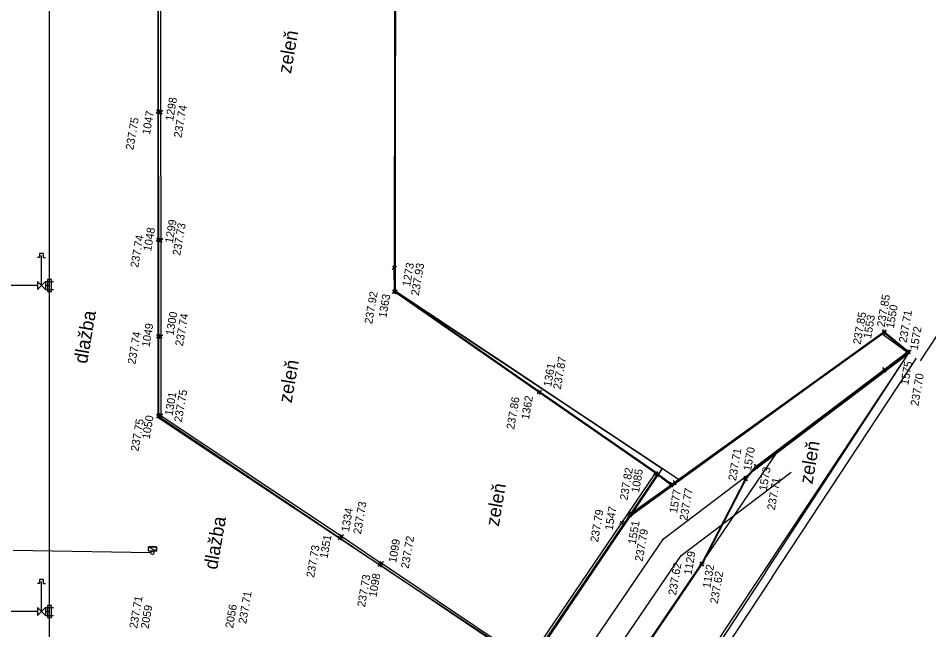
# Model space of a CAD drawing. Extents: x -264205 to -263659, y -1242401 to -1241986.
# Drawn here: x -263790.1 to -263733.2, y -1242222.2 to -1242184 of the extents above; entities that cross this region are included whole.
import ezdxf

# ---------------------------------------------------------------- set-up
doc = ezdxf.new("R2010")
doc.units = 0
for name, color, linetype in [('BOD_CISLO_2-4', 7, 'Continuous'), ('BOD_SYMBOL_2-4', 7, 'Continuous'), ('BOD_VYSKA_2-4', 7, 'Continuous'), ('POPIS_2-4', 7, 'Continuous'), ('PROJEKT_OBRUBNIKY_KOMUNIKACIE', 7, 'Continuous'), ('PROJEKT_TDZ_VODOROVNE', 7, 'Continuous'), ('SITUACIA_DSP_2D', 7, 'Continuous'), ('SO_20-4_OBRUBNIKY_HORNA_HRANA', 7, 'Continuous')]:
    doc.layers.add(name, color=color, linetype=linetype)

msp = doc.modelspace()

# ---------------------------------------------------------------- linework, layer by layer
at = {"layer": 'BOD_SYMBOL_2-4'}
for p, q in [((-263781.219, -1242189.759), (-263781.475, -1242189.939)), ((-263781.257, -1242189.977), (-263781.437, -1242189.721)), ((-263781.075, -1242189.76), (-263781.331, -1242189.94)), ((-263781.113, -1242189.978), (-263781.293, -1242189.722)), ((-263781.217, -1242197.765), (-263781.473, -1242197.945)), ((-263781.255, -1242197.983), (-263781.435, -1242197.727)), ((-263781.07, -1242197.772), (-263781.326, -1242197.952)), ((-263781.108, -1242197.99), (-263781.288, -1242197.734)), ((-263766.482, -1242199.494), (-263766.738, -1242199.674)), ((-263766.52, -1242199.712), (-263766.7, -1242199.456)), ((-263766.48, -1242200.997), (-263766.736, -1242201.177)), ((-263766.518, -1242201.215), (-263766.698, -1242200.959)), ((-263766.433, -1242200.971), (-263766.689, -1242201.151)), ((-263766.471, -1242201.189), (-263766.651, -1242200.933)), ((-263781.25, -1242204.002), (-263781.43, -1242203.746)), ((-263781.106, -1242203.995), (-263781.286, -1242203.739)), ((-263735.895, -1242203.532), (-263736.151, -1242203.712)), ((-263735.894, -1242203.473), (-263736.15, -1242203.653)), ((-263735.933, -1242203.75), (-263736.113, -1242203.494)), ((-263735.932, -1242203.691), (-263736.112, -1242203.435)), ((-263781.212, -1242203.784), (-263781.468, -1242203.964)), ((-263781.068, -1242203.777), (-263781.324, -1242203.957)), ((-263734.424, -1242204.724), (-263734.68, -1242204.904)), ((-263734.462, -1242204.942), (-263734.642, -1242204.686)), ((-263734.342, -1242204.73), (-263734.598, -1242204.91)), ((-263734.38, -1242204.948), (-263734.56, -1242204.692)), ((-263735.882, -1242205.839), (-263736.138, -1242206.019)), ((-263735.854, -1242205.87), (-263736.11, -1242206.05)), ((-263735.92, -1242206.057), (-263736.1, -1242205.801)), ((-263735.892, -1242206.088), (-263736.072, -1242205.832)), ((-263757.438, -1242207.266), (-263757.694, -1242207.446)), ((-263757.41, -1242207.227), (-263757.666, -1242207.407)), ((-263757.476, -1242207.484), (-263757.656, -1242207.228)), ((-263757.448, -1242207.445), (-263757.628, -1242207.189)), ((-263781.212, -1242208.754), (-263781.468, -1242208.934)), ((-263781.25, -1242208.972), (-263781.43, -1242208.716)), ((-263781.065, -1242208.713), (-263781.321, -1242208.893)), ((-263781.103, -1242208.931), (-263781.283, -1242208.675)), ((-263750.206, -1242212.532), (-263750.386, -1242212.276)), ((-263743.888, -1242211.879), (-263744.144, -1242212.059)), ((-263743.861, -1242211.918), (-263744.117, -1242212.098)), ((-263743.926, -1242212.097), (-263744.106, -1242211.841)), ((-263743.899, -1242212.136), (-263744.079, -1242211.88)), ((-263750.168, -1242212.314), (-263750.424, -1242212.494)), ((-263750.049, -1242212.397), (-263750.305, -1242212.577)), ((-263750.022, -1242212.357), (-263750.278, -1242212.537)), ((-263750.087, -1242212.615), (-263750.267, -1242212.359)), ((-263750.06, -1242212.575), (-263750.24, -1242212.319)), ((-263744.547, -1242212.631), (-263744.803, -1242212.811)), ((-263744.585, -1242212.849), (-263744.765, -1242212.593)), ((-263744.507, -1242212.655), (-263744.763, -1242212.835)), ((-263744.545, -1242212.873), (-263744.725, -1242212.617)), ((-263749.18, -1242213.024), (-263749.436, -1242213.204)), ((-263749.168, -1242213.053), (-263749.424, -1242213.233)), ((-263749.218, -1242213.242), (-263749.398, -1242212.986)), ((-263749.142, -1242213.001), (-263749.398, -1242213.181)), ((-263749.206, -1242213.271), (-263749.386, -1242213.015)), ((-263749.18, -1242213.219), (-263749.36, -1242212.963)), ((-263748.961, -1242212.903), (-263749.217, -1242213.083)), ((-263748.999, -1242213.121), (-263749.179, -1242212.865)), ((-263751.761, -1242214.922), (-263752.017, -1242215.102)), ((-263751.799, -1242215.14), (-263751.979, -1242214.884)), ((-263751.701, -1242214.833), (-263751.957, -1242215.013)), ((-263751.739, -1242215.051), (-263751.919, -1242214.795)), ((-263752.267, -1242215.425), (-263752.523, -1242215.605)), ((-263752.305, -1242215.643), (-263752.485, -1242215.387)), ((-263769.787, -1242216.25), (-263770.043, -1242216.43)), ((-263769.825, -1242216.468), (-263770.005, -1242216.212)), ((-263769.87, -1242216.372), (-263770.126, -1242216.552)), ((-263769.908, -1242216.59), (-263770.088, -1242216.334)), ((-263767.295, -1242217.924), (-263767.551, -1242218.104)), ((-263767.333, -1242218.142), (-263767.513, -1242217.886)), ((-263747.289, -1242217.967), (-263747.545, -1242218.147)), ((-263747.327, -1242218.185), (-263747.507, -1242217.929)), ((-263747.289, -1242218.21), (-263747.469, -1242217.954)), ((-263767.373, -1242218.042), (-263767.629, -1242218.222)), ((-263767.411, -1242218.26), (-263767.591, -1242218.004)), ((-263747.251, -1242217.992), (-263747.507, -1242218.172))]:
    msp.add_line(p, q, dxfattribs=at)
at = {"layer": 'PROJEKT_OBRUBNIKY_KOMUNIKACIE'}
for p, q in [((-263766.58, -1242201.01), (-263766.58, -1242144.85)), ((-263758.42, -1242206.43), (-263766.58, -1242201.01)), ((-263736.134, -1242203.7), (-263751.891, -1242215.1)), ((-263736.134, -1242203.7), (-263734.475, -1242204.91)), ((-263742.736, -1242211.145), (-263734.49, -1242204.937)), ((-263757.19, -1242207.25), (-263758.42, -1242206.43)), ((-263748.89, -1242212.77), (-263757.19, -1242207.25)), ((-263794.898, -1242288.032), (-263742.736, -1242211.145)), ((-263798.899, -1242284.125), (-263751.864, -1242215.081)), ((-263751.891, -1242215.1), (-263751.891, -1242215.1)), ((-263743.421, -1242218.608), (-263752.521, -1242232.37))]:
    msp.add_line(p, q, dxfattribs=at)
for points in [[(-263766.58, -1242083.485), (-263766.58, -1242201.01), (-263749.879, -1242212.113), (-263758.153, -1242224.365), (-263781.364, -1242208.936), (-263781.371, -1242084.903), (-263766.58, -1242083.485)], [(-263743.421, -1242218.608), (-263734.49, -1242204.937), (-263734.475, -1242204.91)]]:
    msp.add_lwpolyline(points, dxfattribs=at)
at = {"layer": 'PROJEKT_TDZ_VODOROVNE'}
for p, q in [((-263733.748, -1242205.389), (-263732.096, -1242202.886)), ((-263743.006, -1242218.884), (-263733.993, -1242205.228)), ((-263743.006, -1242218.884), (-263752.106, -1242232.646))]:
    msp.add_line(p, q, dxfattribs=at)
for points in [[(-263831.211, -1242326.873), (-263816.19, -1242319.41), (-263814.291, -1242315.804), (-263813.06, -1242301.353), (-263812.968, -1242299.181), (-263802.618, -1242291.831), (-263801.478, -1242290.893), (-263800.257, -1242289.755), (-263799.049, -1242288.464), (-263798.027, -1242287.218), (-263749.798, -1242216.488), (-263742.736, -1242211.145)], [(-263830.6, -1242328.105), (-263815.26, -1242320.378), (-263813.062, -1242316.188), (-263811.682, -1242301.389), (-263811.608, -1242300.055), (-263801.705, -1242293.023), (-263800.489, -1242292.021), (-263799.197, -1242290.817), (-263797.92, -1242289.454), (-263796.825, -1242288.118), (-263748.697, -1242217.536), (-263741.831, -1242212.341)]]:
    msp.add_lwpolyline(points, dxfattribs=at)
at = {"layer": 'SITUACIA_DSP_2D'}
for p, q in [((-263788.143, -1242250.14), (-263788.143, -1242082.64)), ((-263766.58, -1242083.485), (-263766.58, -1242201.01)), ((-263781.364, -1242208.936), (-263781.371, -1242084.903)), ((-263766.58, -1242201.01), (-263766.58, -1242144.85)), ((-263788.768, -1242198.932), (-263788.893, -1242198.932)), ((-263788.768, -1242198.682), (-263788.768, -1242198.932)), ((-263788.518, -1242198.682), (-263788.768, -1242198.682)), ((-263788.643, -1242200.682), (-263788.643, -1242198.807)), ((-263788.518, -1242198.932), (-263788.518, -1242198.682)), ((-263788.518, -1242198.932), (-263788.393, -1242198.932)), ((-263788.268, -1242200.307), (-263788.268, -1242201.057)), ((-263788.018, -1242200.307), (-263788.268, -1242200.307)), ((-263788.018, -1242201.057), (-263788.018, -1242200.307)), ((-263788.893, -1242200.682), (-263800.593, -1242200.682)), ((-263788.893, -1242200.432), (-263788.893, -1242200.932)), ((-263788.393, -1242200.932), (-263788.893, -1242200.432)), ((-263788.893, -1242200.932), (-263788.393, -1242200.432)), ((-263788.393, -1242200.432), (-263788.393, -1242200.932)), ((-263788.393, -1242200.432), (-263787.893, -1242200.432)), ((-263788.143, -1242200.682), (-263788.393, -1242200.682)), ((-263788.393, -1242200.682), (-263788.143, -1242200.682)), ((-263788.393, -1242200.932), (-263787.893, -1242200.932)), ((-263788.268, -1242201.057), (-263788.018, -1242201.057)), ((-263758.42, -1242206.43), (-263766.58, -1242201.01)), ((-263766.58, -1242201.01), (-263749.879, -1242212.113)), ((-263736.134, -1242203.7), (-263751.891, -1242215.1)), ((-263736.134, -1242203.7), (-263734.475, -1242204.91)), ((-263822.88, -1242337.914), (-263734.49, -1242204.937)), ((-263743.421, -1242218.608), (-263734.49, -1242204.937)), ((-263734.49, -1242204.937), (-263734.475, -1242204.91)), ((-263734.475, -1242204.91), (-263734.475, -1242204.91)), ((-263757.19, -1242207.25), (-263758.42, -1242206.43)), ((-263748.89, -1242212.77), (-263757.19, -1242207.25)), ((-263758.153, -1242224.365), (-263781.364, -1242208.936)), ((-263794.898, -1242288.032), (-263742.736, -1242211.145)), ((-263749.879, -1242212.113), (-263758.153, -1242224.365)), ((-263798.899, -1242284.125), (-263751.864, -1242215.081)), ((-263751.891, -1242215.1), (-263751.891, -1242215.1)), ((-263781.818, -1242217.375), (-263790.409, -1242217.218)), ((-263781.968, -1242216.987), (-263781.468, -1242216.987)), ((-263781.968, -1242217.277), (-263781.968, -1242216.987)), ((-263781.968, -1242216.987), (-263781.468, -1242217.277)), ((-263781.968, -1242216.987), (-263781.468, -1242217.277)), ((-263781.468, -1242216.987), (-263781.968, -1242216.987)), ((-263781.468, -1242217.277), (-263781.968, -1242217.277)), ((-263781.468, -1242216.987), (-263781.468, -1242217.277)), ((-263781.468, -1242217.277), (-263781.468, -1242216.987)), ((-263788.768, -1242219.032), (-263788.768, -1242219.282)), ((-263788.518, -1242219.032), (-263788.768, -1242219.032)), ((-263788.518, -1242219.282), (-263788.518, -1242219.032)), ((-263743.421, -1242218.608), (-263752.521, -1242232.37)), ((-263788.768, -1242219.282), (-263788.893, -1242219.282)), ((-263788.643, -1242221.032), (-263788.643, -1242219.157)), ((-263788.518, -1242219.282), (-263788.393, -1242219.282)), ((-263788.893, -1242220.782), (-263788.893, -1242221.282)), ((-263788.393, -1242221.282), (-263788.893, -1242220.782)), ((-263788.893, -1242221.282), (-263788.393, -1242220.782)), ((-263788.393, -1242220.782), (-263788.393, -1242221.282)), ((-263788.393, -1242220.782), (-263787.893, -1242220.782)), ((-263788.268, -1242220.657), (-263788.268, -1242221.407)), ((-263788.018, -1242220.657), (-263788.268, -1242220.657)), ((-263788.018, -1242221.407), (-263788.018, -1242220.657)), ((-263788.893, -1242221.032), (-263800.593, -1242221.032)), ((-263788.143, -1242221.032), (-263788.393, -1242221.032)), ((-263788.393, -1242221.032), (-263788.143, -1242221.032)), ((-263788.393, -1242221.282), (-263787.893, -1242221.282)), ((-263788.268, -1242221.407), (-263788.018, -1242221.407))]:
    msp.add_line(p, q, dxfattribs=at)
msp.add_circle((-263781.718, -1242217.377), 0.1, dxfattribs=at)
at = {"layer": 'SO_20-4_OBRUBNIKY_HORNA_HRANA'}
for p, q in [((-263736.023, -1242203.622), (-263734.552, -1242204.814)), ((-263736.022, -1242203.563), (-263734.47, -1242204.82)), ((-263750.177, -1242212.487), (-263749.296, -1242213.143)), ((-263750.15, -1242212.447), (-263749.27, -1242213.091)), ((-263744.675, -1242212.721), (-263747.417, -1242218.057)), ((-263744.635, -1242212.745), (-263747.379, -1242218.082)), ((-263751.829, -1242214.923), (-263749.308, -1242213.114)), ((-263752.395, -1242215.515), (-263752.395, -1242215.515)), ((-263758.354, -1242224.285), (-263767.501, -1242218.132)), ((-263758.272, -1242224.164), (-263767.423, -1242218.014))]:
    msp.add_line(p, q, dxfattribs=at)
for points in [[(-263766.587, -1242077.959), (-263766.469, -1242083.522), (-263773.438, -1242084.169), (-263781.388, -1242084.901), (-263781.386, -1242085.716), (-263781.367, -1242092.693), (-263781.36, -1242099.718), (-263781.342, -1242106.76), (-263781.33, -1242113.728), (-263781.339, -1242120.772), (-263781.333, -1242126.494), (-263781.333, -1242132.5), (-263781.342, -1242140.774), (-263781.347, -1242148.817), (-263781.342, -1242156.781), (-263781.344, -1242164.83), (-263781.345, -1242172.787), (-263781.348, -1242180.844), (-263781.347, -1242189.849), (-263781.345, -1242197.855), (-263781.34, -1242203.874), (-263781.34, -1242208.844)], [(-263766.421, -1242083.663), (-263773.417, -1242084.312), (-263781.245, -1242085.033), (-263781.241, -1242085.71), (-263781.224, -1242092.7), (-263781.216, -1242099.721), (-263781.198, -1242106.757), (-263781.186, -1242113.724), (-263781.193, -1242120.791), (-263781.187, -1242126.485), (-263781.19, -1242132.499), (-263781.197, -1242140.771), (-263781.201, -1242148.817), (-263781.201, -1242156.777), (-263781.2, -1242164.831), (-263781.2, -1242172.812), (-263781.205, -1242180.858), (-263781.203, -1242189.85), (-263781.198, -1242197.862), (-263781.196, -1242203.867), (-263781.193, -1242208.803)], [(-263766.471, -1242083.668), (-263766.506, -1242116.681), (-263766.543, -1242144.61), (-263766.583, -1242171.626), (-263766.61, -1242199.584)], [(-263766.421, -1242083.663), (-263766.456, -1242116.681), (-263766.493, -1242144.61), (-263766.533, -1242171.626), (-263766.561, -1242201.061)], [(-263750.296, -1242212.404), (-263757.566, -1242207.356), (-263766.608, -1242201.087), (-263766.61, -1242199.584)], [(-263750.15, -1242212.447), (-263757.538, -1242207.317), (-263766.561, -1242201.061)], [(-263751.889, -1242215.012), (-263749.089, -1242212.993), (-263736.023, -1242203.622)], [(-263749.308, -1242213.114), (-263749.27, -1242213.091), (-263736.022, -1242203.563)], [(-263744.675, -1242212.721), (-263744.016, -1242211.969), (-263736.01, -1242205.929), (-263734.552, -1242204.814)], [(-263744.635, -1242212.745), (-263743.989, -1242212.008), (-263735.982, -1242205.96), (-263734.47, -1242204.82)], [(-263781.34, -1242208.844), (-263769.998, -1242216.462), (-263767.501, -1242218.132)], [(-263781.193, -1242208.803), (-263769.915, -1242216.34), (-263767.423, -1242218.014)], [(-263788.718, -1242269.04), (-263779.575, -1242255.577), (-263771.592, -1242243.806), (-263758.354, -1242224.285), (-263758.272, -1242224.164), (-263750.296, -1242212.404)], [(-263788.598, -1242269.122), (-263779.463, -1242255.663), (-263771.455, -1242243.86), (-263758.151, -1242224.245), (-263750.15, -1242212.447)], [(-263771.894, -1242252.207), (-263767.033, -1242246.951), (-263753.675, -1242227.268), (-263747.417, -1242218.057)], [(-263771.856, -1242252.232), (-263766.995, -1242246.976), (-263753.637, -1242227.293), (-263747.379, -1242218.082)]]:
    msp.add_lwpolyline(points, dxfattribs=at)

# ---------------------------------------------------------------- texts
at = {"layer": 'BOD_CISLO_2-4'}
for s, p in [('1298', (-263780.425, -1242190.447)), ('1047', (-263781.871, -1242191.293)), ('1299', (-263780.451, -1242198.075)), ('1048', (-263781.798, -1242198.572)), ('1273', (-263765.627, -1242200.774)), ('1363', (-263767.113, -1242202.727)), ('1550', (-263735.418, -1242203.39)), ('1300', (-263780.403, -1242203.829)), ('1553', (-263736.838, -1242204.024)), ('1049', (-263781.898, -1242204.554)), ('1572', (-263733.93, -1242204.748)), ('1575', (-263734.516, -1242206.92)), ('1361', (-263756.813, -1242207.036)), ('1301', (-263780.464, -1242208.84)), ('1362', (-263758.202, -1242209.077)), ('1050', (-263781.891, -1242210.302)), ('1570', (-263744.335, -1242212.284)), ('1085', (-263751.331, -1242213.646)), ('1573', (-263743.355, -1242213.523)), ('1577', (-263748.955, -1242214.923)), ('1547', (-263752.98, -1242215.99)), ('1334', (-263769.441, -1242216.089)), ('1551', (-263751.536, -1242216.875)), ('1351', (-263770.781, -1242217.749)), ('1099', (-263766.493, -1242218.018)), ('1129', (-263748.049, -1242218.777)), ('1132', (-263746.878, -1242219.606)), ('1098', (-263767.725, -1242220.165)), ('2059', (-263781.964, -1242222.139)), ('2056', (-263776.684, -1242222.097))]:
    msp.add_text(s, height=0.5, rotation=80.1724, dxfattribs=at).set_placement(p)
at = {"layer": 'BOD_VYSKA_2-4'}
for s, p in [('237.74', (-263779.904, -1242191.484)), ('237.75', (-263782.912, -1242192.254)), ('237.73', (-263779.98, -1242198.843)), ('237.74', (-263782.608, -1242199.593)), ('237.93', (-263765.086, -1242201.345)), ('237.92', (-263767.993, -1242203.111)), ('237.85', (-263735.993, -1242203.306)), ('237.74', (-263779.815, -1242204.495)), ('237.85', (-263737.486, -1242204.393)), ('237.71', (-263734.622, -1242204.284)), ('237.74', (-263782.782, -1242205.628)), ('237.87', (-263756.216, -1242207.193)), ('237.70', (-263733.888, -1242208.233)), ('237.75', (-263779.884, -1242209.247)), ('237.86', (-263759.129, -1242209.698)), ('237.75', (-263782.592, -1242211.064)), ('237.71', (-263745.272, -1242212.9)), ('237.82', (-263752.051, -1242214.112)), ('237.71', (-263742.846, -1242214.734)), ('237.77', (-263748.316, -1242215.39)), ('237.73', (-263768.694, -1242216.233)), ('237.79', (-263753.89, -1242216.73)), ('237.79', (-263751.107, -1242217.942)), ('237.72', (-263765.714, -1242218.378)), ('237.73', (-263771.622, -1242218.949)), ('237.62', (-263749.02, -1242220.049)), ('237.62', (-263746.411, -1242220.572)), ('237.73', (-263768.444, -1242220.783)), ('237.71', (-263782.674, -1242222.12)), ('237.71', (-263775.862, -1242221.828))]:
    msp.add_text(s, height=0.5, rotation=80.1724, dxfattribs=at).set_placement(p)
at = {"layer": 'POPIS_2-4'}
for s, p in [('zeleň', (-263773.067, -1242187.494)), ('dlažba', (-263785.803, -1242205.598)), ('zeleň', (-263773.028, -1242208.056)), ('zeleň', (-263740.5, -1242213.113)), ('zeleň', (-263760.089, -1242215.761)), ('dlažba', (-263777.68, -1242218.453))]:
    msp.add_text(s, height=0.8437, rotation=80.1724, dxfattribs=at).set_placement(p)

doc.saveas('drawing.dxf')
